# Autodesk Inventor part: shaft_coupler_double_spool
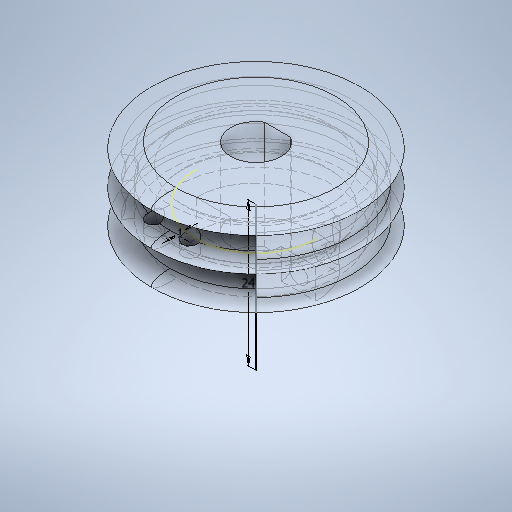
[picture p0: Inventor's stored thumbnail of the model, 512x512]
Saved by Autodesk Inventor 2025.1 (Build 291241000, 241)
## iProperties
Created: 2025-03
Part Number: shaft_coupler_double_spool
Material: Genérico
Document SubType Name: Modeling
Designer: Usuario
Density: 1 g/cm^3
Appearance: Valor por defecto
Author: Usuario
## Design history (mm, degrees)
sketch "Boceto1"
  geometry: L1 (-0.079, -4.178)-(-0.079, -3.578); L2 (-0.079, -3.578)-(2.2, -3.578); L3 (-0.079, -3.578)-(-2.2, -3.578); C1 r 10 at (0, 0); A1 r 4.2 centre (0, 0) between (2.2, -3.578) and (-2.2, -3.578); 1 further point
  constraints: 6 end point, 2 centre point, 2 coincident, 2 point on circle, 1 perpendicular, 1 point on line, 1 vertical
  dimensions: "d0" = 8.4 diameter of A1; "d1" = 20 diameter of C1; "d2" = 0.6 distance of L1.start L1.end
extrude "Extrusión1" new body sketch "Boceto1" stored distance "d3" = 8; taper "d4" = 0 deg
sketch "Boceto2"
  geometry: L1 (-2.2, 3.578)-(2.2, 3.578) reference; L2 (2.2, 3.578)-(-2.2, 3.578); L3 (-4.2, 0)-(-10, 0); L4 (4.05, 0)-(10, 0); A1 r 10 centre (0, 0) between (10, 0) and (-10, 0); A2 r 4.2 centre (0, 0) between (4.2, 0) and (2.2, 3.578); A3 r 4.2 centre (0, 0) between (-2.2, 3.578) and (-4.2, 0); 2 further points
  constraints: 6 end point, 6 point on circle, 3 centre point, 2 coincident, 1 collinear, 1 horizontal, 1 point on line
extrude "Extrusión2" join sketch "Boceto2" distance "d5" = 5; taper "d6" = 0 deg
node "Plano de trabajo1"
mirror "Simetría1"
node "Plano de trabajo2"
sketch "Boceto3"
  geometry: L1 (0, 0)-(5, 0) reference; L2 (0, 0)-(0, 2.9); L3 (0, 5.8)-(0, 0) reference; L4 (0, 2.9)-(2.5, 2.9); C1 r 1.5 at (2.5, 2.9); 1 further point
  constraints: 4 end point, 1 centre point, 1 coincident, 1 midpoint, 1 perpendicular
  dimensions: "d7" = 2.9 distance of L1.start L2.end (derived); "d8" = 2.5 distance of L2.end L4.end; "d9" = 3 diameter of C1
extrude "screw1" cut sketch "Boceto3" distance "d10" = 9; taper "d11" = 0 deg
node "Plano de trabajo3"
sketch "Boceto4"
  geometry: C1 r 1.5 at (2.5, 2.9) reference; C2 r 1.5 at (2.5, 2.9); C3 r 3.75 at (2.5, 2.9); 1 further point
  constraints: 2 centre point, 2 coincident, 1 concentric
  dimensions: "d15" = 7.5 diameter of C3
extrude "Extrusión4" cut sketch "Boceto4" distance "d13" = 9; taper "d14" = 0 deg
node "Plano de trabajo5"
sketch "Boceto7"
  geometry: L1 (0, -10)-(0, -11); A1 r 10 centre (0, 0) between (-10, 0) and (10, 0) reference; 1 further point
  constraints: 2 end point, 1 point on circle, 1 vertical
  dimensions: "d29" = 1 distance of L1.start L1.end
node "Plano de trabajo6"
feature "Rosca5" dims "d47" = 6, "d48" = 0
sketch "Boceto12"
  geometry: L1 (-4, 10)-(20, 10)
  constraints: 2 end point, 1 horizontal
  dimensions: "d53" = 24 distance of L1.start L1.end
feature "Engrosado3" dims "d58" = 5, "d59" = 5
node "double_spool"
sketch "Boceto15"
  geometry: L1 (0, 4)-(0, -9) reference; L2 (0, -9)-(0, -2.5); L3 (0, -2.5)-(1, -2.5); L4 (0, -9)-(1, -9); L5 (0, 4)-(1, 4); L6 (7.5, -2.5)-(9.544, -2.5); L7 (0, -2.5)-(0, 0.75); L8 (1.987, 0.75)-(8.456, 0.75); L9 (0, -2.5)-(0, -5.75); L10 (1.987, -5.75)-(9.922, -5.75); L11 (1, 4)-(3.275, 4); L12 (1, -9)-(3.275, -9); A1 r 6.4 centre (7.5, -9) between (4.349, -3.429) and (1.987, -5.75); A2 r 6.4 centre (7.5, 4) between (1.987, 0.75) and (4.349, -1.571); A3 r 6.5 centre (1, -2.5) between (1.1, 3.999) and (1, 4); A4 r 3.001 centre (4.483, -0.916) between (4.349, 2.082) and (1.987, 0.75); A5 r 3.001 centre (4.483, -4.084) between (1.987, -5.75) and (4.349, -7.082); 6 further points; 3 other entities
  constraints: 22 end point, 11 point on circle, 7 symmetric about line, 6 horizontal, 5 centre point, 3 perpendicular, 3 point on line, 2 coincident, 2 midpoint, 14 other
  dimensions: "d68" = 3.25 distance of L2.end L7.end; "d69" = 3.25 distance of L2.end L9.end
revolve "cable_guide" sketch "Boceto15" stored, may be unused: angle "d70" = 360 deg
node "cable_fix_input"
sketch "Boceto16"
  geometry: L1 (0, 17.5)-(0, 14.349); L2 (0, 11)-(3.026, 14.026); L3 (0, 11)-(4.28, 11); L4 (0, 11)-(0, 17.5); C1 r 1.25 at (3.026, 14.026); C2 r 1.25 at (-3.026, 14.026); A1 r 14.349 centre (0, 0) between (0, 14.349) and (3.026, 14.026) reference; 2 further points
  constraints: 8 end point, 2 centre point, 1 coincident, 1 collinear, 1 equal length, 1 horizontal, 1 point on circle, 1 symmetric about line, 1 vertical alignment, 2 other
  dimensions: "d73" = 45 deg angle of L3 L2; "d74" = 2.5 diameter of C1
extrude "cable_fixpoint" cut sketch "Boceto16" stored distance "d75" = 5; taper "d76" = 0 deg
node "Plano de trabajo11"
sketch "Boceto17"
  geometry: L1 (-1.571, -14.349)-(-1.571, 14.349) reference; L2 (2.082, -14.349)-(2.082, 14.349) reference; L3 (-1.571, 14.349)-(-1.571, 15.849); L4 (-1.571, 14.349)-(-2.5, 14.349); L5 (-2.5, 14.349)-(-2.5, 17.64); L6 (-1.571, 14.349)-(3.052, 14.349); L7 (3.052, 14.349)-(3.052, 17.785); L8 (-1.571, 14.349)-(-2.5, 16.509); L9 (2.082, 14.349)-(3.052, 16.547); L10 (-3.43, 14.349)-(-2.5, 16.509); L11 (-7.083, 14.349)-(-8.052, 16.547); A1 r 4 centre (0.256, 17.908) between (-1.571, 14.349) and (2.082, 14.349); A2 r 4 centre (0.256, 19.408) between (-2.5, 16.509) and (3.052, 16.547); A3 r 4 centre (-5.256, 19.408) between (-8.052, 16.547) and (-2.5, 16.509); A4 r 4 centre (-5.256, 17.908) between (-7.083, 14.349) and (-3.43, 14.349); 6 further points
  constraints: 18 end point, 9 point on circle, 5 symmetric about line, 4 centre point, 3 perpendicular, 2 point on line, 1 horizontal, 1 vertical, 2 other
  dimensions: "d81" = 4 radius of A1; "d83" = 4 radius of A2; "d84" = 0.9295 distance of L1.end L4.end
revolve "cable_cover" sketch "Boceto17" stored, may be unused: angle "d85" = 270 deg
node "Sólido1"
other parameters: "d12" = 6, "d30" = 90 deg, "d60" = 90 deg, "d65" = 12.8, "d77" = 45 deg
